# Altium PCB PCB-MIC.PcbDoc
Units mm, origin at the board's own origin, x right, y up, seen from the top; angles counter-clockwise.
Board outline 24 x 22 mm, 2 copper layers (F.Cu, B.Cu); 6 components, 7 nets, 53 pads, 5 vias.
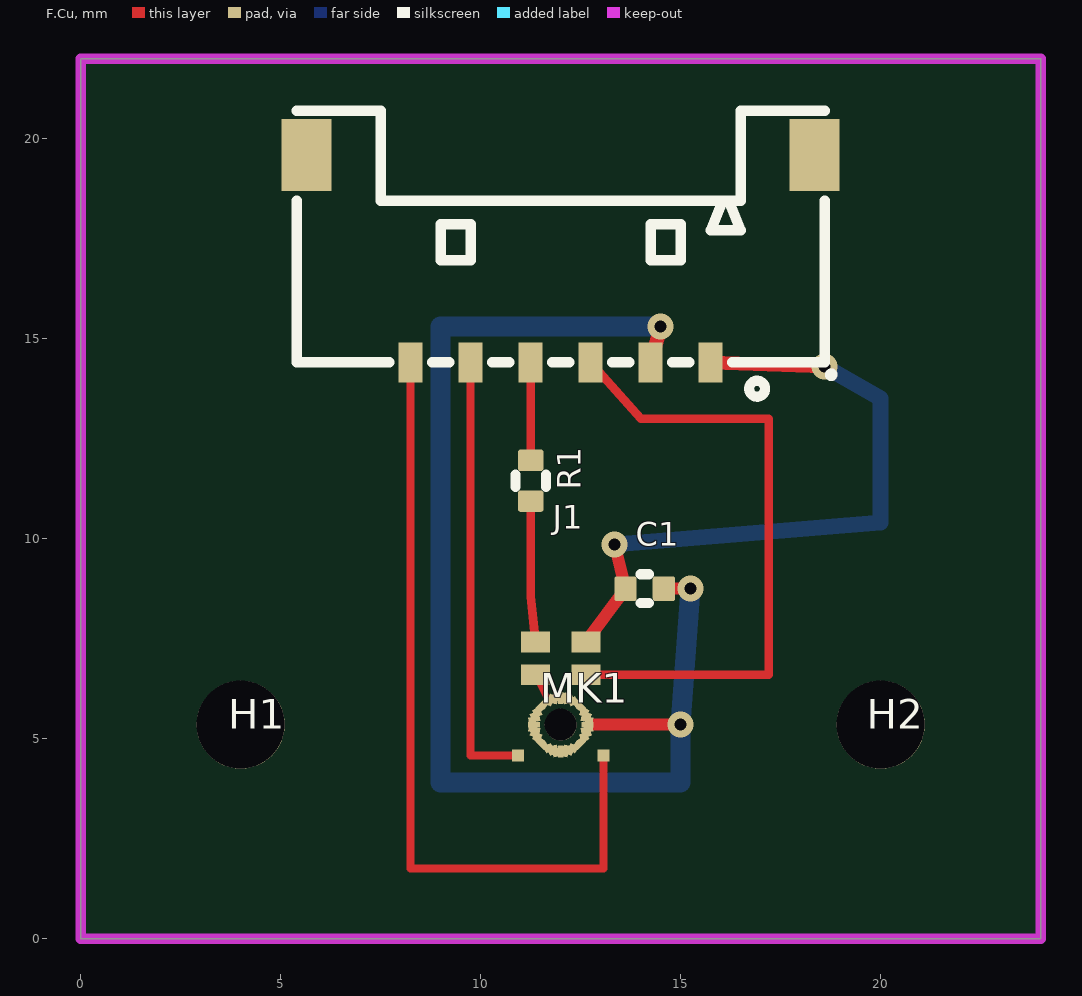
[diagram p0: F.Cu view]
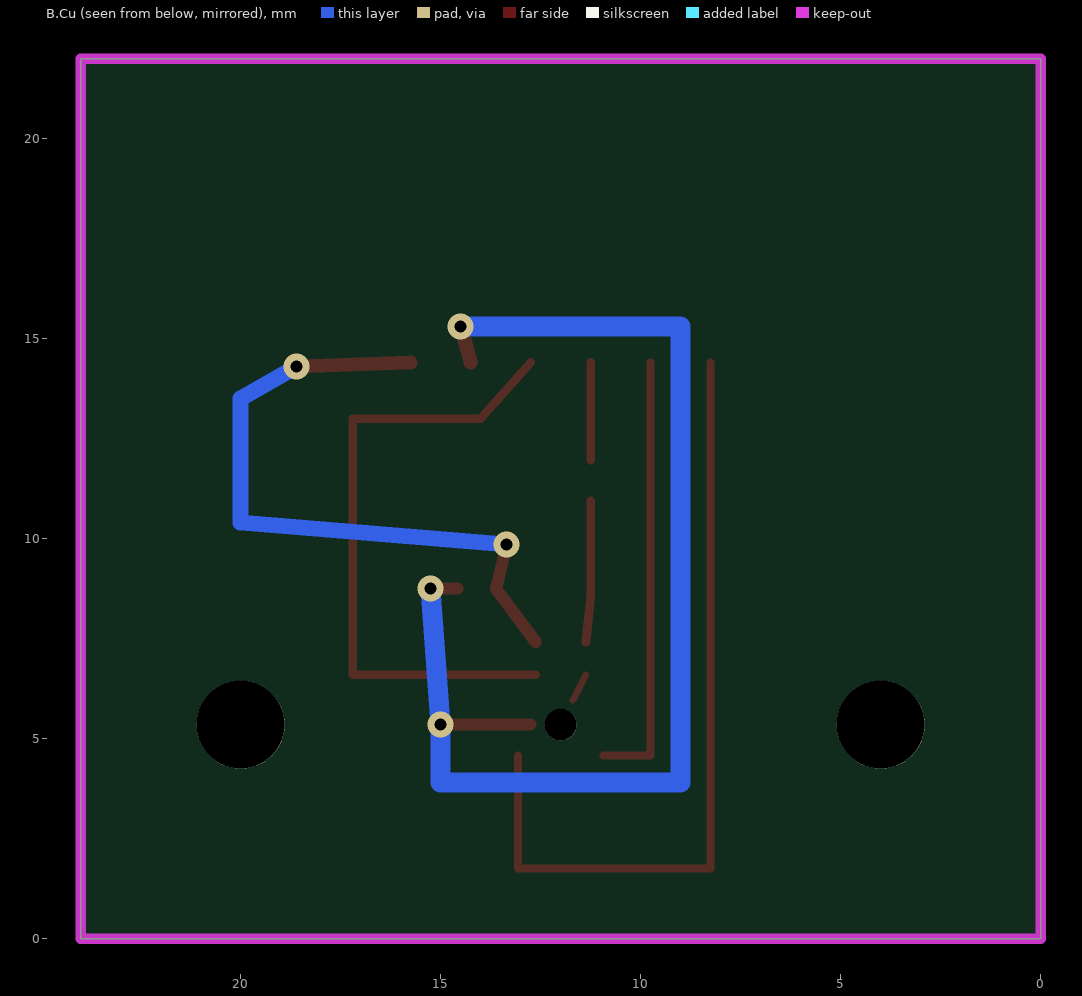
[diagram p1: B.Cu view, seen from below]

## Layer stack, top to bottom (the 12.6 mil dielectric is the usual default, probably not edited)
F.Mask: solder mask 0.0102, Solder Resist, Dk 3.5
F.Cu: signal copper 0.0356
Dielectric 1: dielectric 0.32, FR-4, Dk 4.8
B.Cu: signal copper 0.0356
B.Mask: solder mask 0.0102, Solder Resist, Dk 3.5

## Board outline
0,0 0,22 24,22 24,0 0,0

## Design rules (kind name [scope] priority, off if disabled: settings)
AssemblyTestPointUsage [All] p1 off:
Clearance MK1_Internal_Acoustic_ClearanceInComponent('MK1')MK1_Internal_Acoustic_ClearanceInComponent('MK1')InComponent('MK1')MK1_Internal_Acoustic_Clearance [IsPad && (Name = 'MK1-3') vs IsPad && (Name = 'MK1-Un1')] p1: gap=0.1 ignorepadtopadclearanceinfootprint=FALSE // EVT-PRE-20: 0.10 mm only between MK1 pad 3 manufacturer land and the 0.8 mm acoustic NPTH
Clearance MK1_Manufacturer_Copper_0p125mm [IsPad && (Name = 'MK1-3') vs IsPad && InComponent('MK1') && (Name <> 'MK1-3') && (Name <> 'MK1-Un1')] p2: gap=0.125 ignorepadtopadclearanceinfootprint=FALSE // EVT-PRE-20: 0.125 mm between MK1 pad 3 manufacturer ground land and ordinary MK1 pads; acoustic NPTH excluded
Clearance "Clearence 0,2_NetClass" [InNetClass('Default')] p3: gap=0.2 ignorepadtopadclearanceinfootprint=FALSE
FabricationTestPointUsage [All] p1 off: valid=0 allowmultiple=FALSE
MinimumSolderMaskSliver [All] p1: minsoldermaskwidth=0
PolygonConnect [All] p1: connectstyle=Direct reliefconductorwidth=0.254 reliefentries=4 polygonreliefangle="90 Angle" airgapwidth=0.254
RoutingVias [All] p1: holewidth=0.3 width=0.6 viastyle="Through Hole" minholewidth=0.3 minwidth=0.5 maxholewidth=0.711 maxwidth=1.27
SilkToSilkClearance [All] p1: silktosilkclearance=0
SilkToSolderMaskClearance [IsPad] p1: minsilkscreentomaskgap=0 clearancetoexposedcopper=TRUE
SolderMaskExpansion [All] p1: expansion=0 istentingtop=FALSE
Width [All] p1: maxlimit=10 minlimit=0.15 preferedwidth=0.2 minimp=50.000000 maximp=50.000000 favimp=50.000000
25 further rules are at their usual default settings.

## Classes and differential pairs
net class Default: 1V8_MIC AAD_CFG GND MIC_WAKE PDM_CLK PDM_DATA PDM_DATA_MIC

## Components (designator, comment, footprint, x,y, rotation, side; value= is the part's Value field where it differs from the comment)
C1 "Comment" C_0402_1005Metric 14.1,8.75 r0 top value="100nF X7R"
H1 "Comment" ? 4,5.35 r0 top value=M2_CLEARANCE_NPTH_2.2
H2 "Comment" ? 20,5.35 r0 top value=M2_CLEARANCE_NPTH_2.2
J1 "Comment" Molex_5040500691 12,17 r180 top value=5040500691
MK1 "Comment" T5838_RevA 12,6 r0 top value=T5838
R1 "Comment" R_0402_1005Metric 11.25,11.45 r270 top value="0R EVT_SI_TUNE"

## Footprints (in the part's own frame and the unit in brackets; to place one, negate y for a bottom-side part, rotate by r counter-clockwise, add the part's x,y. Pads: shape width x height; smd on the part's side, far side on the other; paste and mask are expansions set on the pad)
C_0402_1005Metric [mm]
  rrect25% 0.56x0.62 smd mask+0: 1(-0.48,0) 2(0.48,0)
  silkscreen extent -0.11,-0.36 0.11,0.36
Molex_5040500691 [mm]
  rect 0.6x1 smd paste+0 mask+0: 1(-3.75,2.59) 2(-2.25,2.59) 3(-0.75,2.59) 4(0.75,2.59) 5(2.25,2.59) 6(3.75,2.59)
  rect 1.25x1.8 smd mask+0: Un1(-6.35,-2.59) Un2(6.35,-2.59)
  silkscreen extent -6.79,-3.7 6.6,3.45
R_0402_1005Metric [mm]
  rrect25% 0.54x0.64 smd mask+0: 1(-0.51,0) 2(0.51,0)
  silkscreen extent -0.15,-0.38 0.15,0.38
T5838_RevA [mm]
  rect 0.725x0.522 smd paste-0.05 mask+0: 1(-0.63,1.42) 2(-0.63,0.6) 6(0.63,0.6) 7(0.63,1.42)
  rect 0.3x0.146 smd paste-0.3 mask+0: 3(-0.673,-0.65) 3(0.673,-0.65)
  rect 0.146x0.3 smd rot 78.75 paste-0.3 mask+0: 3(-0.66,-0.781) 3(0.66,-0.519)
  rect 0.146x0.3 smd rot 101.25 paste-0.3 mask+0: 3(-0.66,-0.519) 3(0.66,-0.781)
  rect 0.146x0.3 smd rot 67.5 paste-0.3 mask+0: 3(-0.621,-0.907) 3(0.621,-0.393)
  rect 0.146x0.3 smd rot 112.5 paste-0.3 mask+0: 3(-0.621,-0.393) 3(0.621,-0.907)
  rect 0.146x0.3 smd rot 56.25 paste-0.3 mask+0: 3(-0.559,-1.024) 3(0.559,-0.276)
  rect 0.146x0.3 smd rot 123.75 paste-0.3 mask+0: 3(-0.559,-0.276) 3(0.559,-1.024)
  rect 0.146x0.3 smd rot 45 paste-0.3 mask+0: 3(-0.476,-1.126) 3(0.476,-0.174)
  rect 0.146x0.3 smd rot 135 paste-0.3 mask+0: 3(-0.476,-0.174) 3(0.476,-1.126)
  rect 0.146x0.3 smd rot 33.75 paste-0.3 mask+0: 3(-0.374,-1.209) 3(0.374,-0.091)
  rect 0.146x0.3 smd rot 146.25 paste-0.3 mask+0: 3(-0.374,-0.091) 3(0.374,-1.209)
  rect 0.146x0.3 smd rot 22.5 paste-0.3 mask+0: 3(-0.257,-1.271) 3(0.257,-0.029)
  rect 0.146x0.3 smd rot 157.5 paste-0.3 mask+0: 3(-0.257,-0.029) 3(0.257,-1.271)
  rect 0.146x0.3 smd rot 11.25 paste-0.3 mask+0: 3(-0.131,-1.31) 3(0.131,0.01)
  rect 0.146x0.3 smd rot 168.75 paste-0.3 mask+0: 3(-0.131,0.01) 3(0.131,-1.31)
  rect 0.146x0.3 smd paste-0.3 mask+0: 3(0,-1.322) 3(0,0.023)
  rect 0.3x0.3 smd paste-0.015 mask+0: 4(-1.07,-1.42) 5(1.07,-1.42)
  round 0.8 hole 0.8 paste-2539.97 mask+0: Un1(0,-0.65)
? [mm]
  round 2.2 hole 2.2 paste-2539.97 mask+0: Un1(0,0)

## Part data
C1: library part C_0402_1005Metric, "Capacitor SMD 0402 (1005 Metric), square (rectangular) end terminal, IPC-7351 nominal, (Body size source: IPC-SM-782 page 76, https://www.pcb-3d.com/wordpress/wp-content/uploads/ipc-sm-782a_amendment_1_and_2.pdf), generated with kicad-footprint-generator"
J1: library part Molex_5040500691, LCSC Part=C563981
MK1: library part T5838_RevA
R1: library part R_0402_1005Metric, "Resistor SMD 0402 (1005 Metric), square (rectangular) end terminal, IPC-7351 nominal, (Body size source: IPC-SM-782 page 72, https://www.pcb-3d.com/wordpress/wp-content/uploads/ipc-sm-782a_amendment_1_and_2.pdf), generated with kicad-footprint-generator"

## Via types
v1: diameter 0.65, hole 0.3, F.Cu to B.Cu, tented both sides, 5 vias

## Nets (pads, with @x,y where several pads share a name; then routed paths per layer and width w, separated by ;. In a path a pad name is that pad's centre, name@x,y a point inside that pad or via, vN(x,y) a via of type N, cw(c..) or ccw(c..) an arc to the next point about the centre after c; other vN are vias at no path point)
1V8_MIC: C1.1 J1.1 MK1.7 | length 17
  F.Cu w0.3: MK1.7 C1.1 v1(13.35,9.85)
  F.Cu w0.35: J1.1 v1(18.6,14.3)
  B.Cu w0.4: v1(13.35,9.85) 20,10.4 20,13.5 v1(18.6,14.3)
AAD_CFG: J1.6 MK1.5 | length 20.3
  F.Cu w0.2: J1.6 8.25,1.75 13.07,1.75 MK1.5
GND: C1.2 J1.2 MK1.2 MK1.3 | length 32.3
  F.Cu w0.16: MK1.2 MK1.3@11.695,5.96
  F.Cu w0.3: MK1.3@12.75,5.35 v1(15,5.35) ; C1.2 v1(15.25,8.75)
  F.Cu w0.35: J1.2 v1(14.5,15.3)
  B.Cu w0.5: v1(14.5,15.3) 9,15.3 9,3.9 15,3.9 v1(15,5.35) v1(15.25,8.75)
MIC_WAKE: J1.5 MK1.4 | length 11
  F.Cu w0.2: J1.5 9.75,4.58 MK1.4
PDM_CLK: J1.3 MK1.6 | length 16.1
  F.Cu w0.22: MK1.6 17.2,6.6 17.2,13 14,13 J1.3
PDM_DATA: J1.4 R1.1 | length 2.5
  F.Cu w0.22: R1.1 J1.4
PDM_DATA_MIC: MK1.1 R1.2 | length 3.5
  F.Cu w0.22: R1.2 11.25,8.55 MK1.1
pads on no net: H1.Un1 H2.Un1 J1.Un1 J1.Un2 MK1.Un1

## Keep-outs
Edge.Cuts:
  lines w0: 0,0 24,0 24,22 0,22 0,0
  lines w0.254: 0,0 24,0 24,22 0,22 0,0

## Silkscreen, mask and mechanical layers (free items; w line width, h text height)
F.Paste:
  circle w0.254: c12,5.35 r0.687
F.Fab:
  lines w0.254: 10.675,4.25 13.325,4.25 13.325,7.75 10.675,7.75 10.675,4.25
  text "PCB-MIC Rev.A MECHANICAL FREEZE - NOT FOR MANUFACTURE" at 6.691,0.6 h0.7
